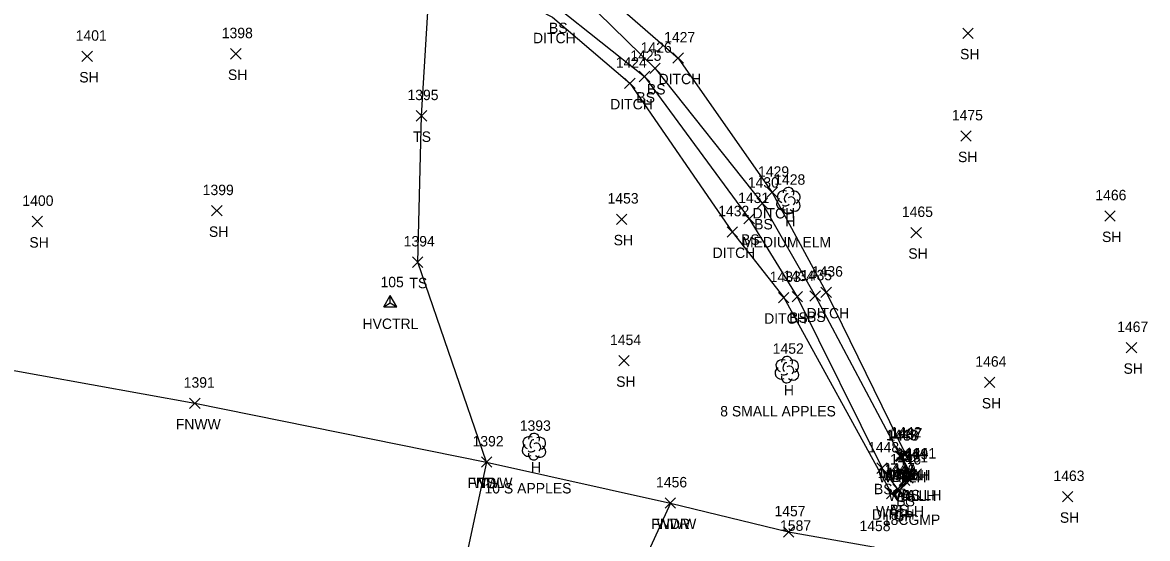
# Model space of a CAD drawing. Extents: x 1629176 to 1637209, y 606063 to 610167.
# Drawn here: x 1629563.1 to 1629778.6, y 606851.1 to 606950 of the extents above; entities that cross this region are included whole.
import ezdxf

# ---------------------------------------------------------------- set-up
doc = ezdxf.new("R2010")
doc.units = 0
for name, color, linetype in [('C_A', 7, 'Continuous'), ('C_I', 7, 'Continuous'), ('CPSM', 7, 'Continuous'), ('D_A', 7, 'Continuous'), ('D_C', 7, 'Continuous'), ('D_I', 7, 'Continuous'), ('D_TIC', 7, 'Continuous'), ('DD', 7, 'Continuous'), ('DHW', 7, 'Continuous'), ('L_A', 7, 'Continuous'), ('L_C', 7, 'Continuous'), ('L_I', 7, 'Continuous'), ('L_TIC', 7, 'Continuous'), ('LAWA', 7, 'Continuous'), ('LELB', 7, 'Continuous'), ('LFNC', 7, 'Continuous'), ('LTD', 7, 'Continuous'), ('R_A', 7, 'Continuous'), ('R_I', 7, 'Continuous'), ('RGP', 7, 'Continuous')]:
    doc.layers.add(name, color=color, linetype=linetype)

msp = doc.modelspace()

# ---------------------------------------------------------------- linework, layer by layer
at = {"layer": 'CPSM'}
for p, q in [((1629632.29, 606895.57), (1629633.54, 606897.73)), ((1629634.79, 606895.57), (1629633.54, 606897.73)), ((1629633.54, 606896.29), (1629633.54, 606897.73)), ((1629632.29, 606895.57), (1629633.54, 606896.29)), ((1629632.29, 606895.57), (1629634.79, 606895.57)), ((1629633.54, 606896.29), (1629633.54, 606896.29)), ((1629633.54, 606896.29), (1629634.79, 606895.57))]:
    msp.add_line(p, q, dxfattribs=at)
at = {"layer": 'D_TIC'}
for points in [[(1629687.69, 606942.21), (1629689.69, 606944.21)], [(1629689.69, 606942.21), (1629687.69, 606944.21)], [(1629678.43, 606937.38), (1629680.43, 606939.38)], [(1629680.43, 606937.38), (1629678.43, 606939.38)], [(1629705.7, 606916.47), (1629707.7, 606918.47)], [(1629707.7, 606916.47), (1629705.7, 606918.47)], [(1629698.06, 606908.9), (1629700.06, 606910.9)], [(1629700.06, 606908.9), (1629698.06, 606910.9)], [(1629716.05, 606897.33), (1629718.05, 606899.33)], [(1629718.05, 606897.33), (1629716.05, 606899.33)], [(1629707.92, 606896.3), (1629709.92, 606898.3)], [(1629709.92, 606896.3), (1629707.92, 606898.3)], [(1629730.48, 606865.89), (1629732.48, 606867.89)], [(1629732.48, 606865.89), (1629730.48, 606867.89)], [(1629731.2, 606866.29), (1629733.21, 606868.29)], [(1629733.21, 606866.29), (1629731.2, 606868.29)], [(1629731.2, 606866.29), (1629733.21, 606868.29)], [(1629733.21, 606866.29), (1629731.2, 606868.29)], [(1629731.71, 606861.74), (1629733.71, 606863.74)], [(1629733.71, 606861.74), (1629731.71, 606863.74)], [(1629732.34, 606862.35), (1629734.34, 606864.35)], [(1629734.34, 606862.35), (1629732.34, 606864.35)], [(1629733.3, 606862.47), (1629735.3, 606864.47)], [(1629735.3, 606862.47), (1629733.3, 606864.47)], [(1629728.58, 606858.74), (1629730.58, 606860.74)], [(1629730.58, 606858.74), (1629728.58, 606860.74)], [(1629730, 606859.35), (1629732, 606861.35)], [(1629732, 606859.35), (1629730, 606861.35)]]:
    msp.add_lwpolyline(points, dxfattribs=at)
at = {"layer": 'DD'}
for points in [[(1629579.49, 606988.83), (1629611.81, 606981.94), (1629648.15, 606971.51), (1629669.27, 606960.14), (1629688.69, 606943.21), (1629706.7, 606917.47), (1629717.05, 606898.33), (1629732.21, 606867.29)], [(1629578.34, 606981.92), (1629612.83, 606972), (1629644.13, 606961.63), (1629664.65, 606951.05), (1629679.43, 606938.38), (1629699.06, 606909.9), (1629708.92, 606897.3), (1629729.58, 606859.74)]]:
    msp.add_lwpolyline(points, dxfattribs=at)
at = {"layer": 'DHW'}
for points in [[(1629732.21, 606867.29), (1629731.48, 606866.89), (1629733.34, 606863.35), (1629731, 606860.35), (1629734.3, 606863.47)], [(1629734.3, 606863.47), (1629732.21, 606867.29)]]:
    msp.add_lwpolyline(points, dxfattribs=at)
at = {"layer": 'L_TIC'}
for points in [[(1629743.21, 606946.97), (1629745.21, 606948.97)], [(1629745.21, 606946.97), (1629743.21, 606948.97)], [(1629574.48, 606942.54), (1629576.48, 606944.54)], [(1629576.48, 606942.54), (1629574.48, 606944.54)], [(1629602.95, 606943.02), (1629604.95, 606945.02)], [(1629604.95, 606943.02), (1629602.95, 606945.02)], [(1629683.26, 606940.24), (1629685.26, 606942.24)], [(1629685.26, 606940.24), (1629683.26, 606942.24)], [(1629681.24, 606938.68), (1629683.24, 606940.68)], [(1629683.24, 606938.68), (1629681.24, 606940.68)], [(1629638.52, 606931.15), (1629640.52, 606933.15)], [(1629640.52, 606931.15), (1629638.52, 606933.15)], [(1629742.82, 606927.27), (1629744.82, 606929.27)], [(1629744.82, 606927.27), (1629742.82, 606929.27)], [(1629703.81, 606914.38), (1629705.81, 606916.38)], [(1629705.81, 606914.38), (1629703.81, 606916.38)], [(1629599.31, 606912.95), (1629601.31, 606914.95)], [(1629601.31, 606912.95), (1629599.31, 606914.95)], [(1629564.92, 606910.89), (1629566.92, 606912.89)], [(1629566.92, 606910.89), (1629564.92, 606912.89)], [(1629676.85, 606911.33), (1629678.85, 606913.33)], [(1629678.85, 606911.33), (1629676.85, 606913.33)], [(1629701.3, 606911.43), (1629703.3, 606913.43)], [(1629703.3, 606911.43), (1629701.3, 606913.43)], [(1629770.4, 606911.96), (1629772.4, 606913.96)], [(1629772.4, 606911.96), (1629770.4, 606913.96)], [(1629733.29, 606908.76), (1629735.29, 606910.76)], [(1629735.29, 606908.76), (1629733.29, 606910.76)], [(1629637.8, 606903.11), (1629639.8, 606905.11)], [(1629639.8, 606903.11), (1629637.8, 606905.11)], [(1629710.51, 606896.48), (1629712.51, 606898.48)], [(1629712.51, 606896.48), (1629710.51, 606898.48)], [(1629713.93, 606896.63), (1629715.93, 606898.63)], [(1629715.93, 606896.63), (1629713.93, 606898.63)], [(1629774.53, 606886.71), (1629776.53, 606888.71)], [(1629776.53, 606886.71), (1629774.53, 606888.71)], [(1629677.33, 606884.21), (1629679.33, 606886.21)], [(1629679.33, 606884.21), (1629677.33, 606886.21)], [(1629747.37, 606880.07), (1629749.37, 606882.07)], [(1629749.37, 606880.07), (1629747.37, 606882.07)], [(1629595.1, 606876.05), (1629597.1, 606878.05)], [(1629597.1, 606876.05), (1629595.1, 606878.05)], [(1629650.99, 606864.79), (1629652.99, 606866.79)], [(1629652.99, 606864.79), (1629650.99, 606866.79)], [(1629650.99, 606864.79), (1629652.99, 606866.79)], [(1629652.99, 606864.79), (1629650.99, 606866.79)], [(1629650.99, 606864.79), (1629652.99, 606866.79)], [(1629652.99, 606864.79), (1629650.99, 606866.79)], [(1629730.19, 606865.97), (1629732.19, 606867.97)], [(1629732.19, 606865.97), (1629730.19, 606867.97)], [(1629730.19, 606865.97), (1629732.19, 606867.97)], [(1629732.19, 606865.97), (1629730.19, 606867.97)], [(1629731.05, 606866.5), (1629733.05, 606868.5)], [(1629733.05, 606866.5), (1629731.05, 606868.5)], [(1629726.76, 606863.63), (1629728.76, 606865.63)], [(1629728.76, 606863.63), (1629726.76, 606865.63)], [(1629726.76, 606863.63), (1629728.76, 606865.63)], [(1629728.76, 606863.63), (1629726.76, 606865.63)], [(1629731.04, 606861.32), (1629733.04, 606863.32)], [(1629733.04, 606861.32), (1629731.04, 606863.32)], [(1629732.06, 606862.46), (1629734.06, 606864.46)], [(1629734.06, 606862.46), (1629732.06, 606864.46)], [(1629729.79, 606859.62), (1629731.79, 606861.62)], [(1629731.79, 606859.62), (1629729.79, 606861.62)], [(1629686.21, 606856.94), (1629688.21, 606858.94)], [(1629688.21, 606856.94), (1629686.21, 606858.94)], [(1629686.21, 606856.94), (1629688.21, 606858.94)], [(1629688.21, 606856.94), (1629686.21, 606858.94)], [(1629762.32, 606858.16), (1629764.32, 606860.16)], [(1629764.32, 606858.16), (1629762.32, 606860.16)], [(1629708.84, 606851.4), (1629710.84, 606853.4)], [(1629710.84, 606851.4), (1629708.84, 606853.4)]]:
    msp.add_lwpolyline(points, dxfattribs=at)
at = {"layer": 'LAWA'}
for points in [[(1629651.99, 606865.79), (1629643.99, 606828.57), (1629642.89, 606813.88), (1629664.41, 606817.56), (1629675.67, 606832.68)], [(1629687.21, 606857.94), (1629675.67, 606832.68)]]:
    msp.add_lwpolyline(points, dxfattribs=at)
at = {"layer": 'LELB'}
for points in [[(1629651.99, 606865.79), (1629638.8, 606904.11), (1629639.52, 606932.15), (1629641.08, 606957.38), (1629605.09, 606970.25), (1629580.18, 606977), (1629580.06, 606977.06), (1629573.73, 606982), (1629574.6, 606989.84), (1629579.49, 606988.83)], [(1629578.44, 606986.01), (1629578.11, 606983.58), (1629612.04, 606975.09), (1629645.79, 606965.11), (1629665.51, 606952.99), (1629682.24, 606939.68), (1629702.3, 606912.43), (1629711.51, 606897.48), (1629727.76, 606864.63)], [(1629578.44, 606986.01), (1629611.74, 606978.59), (1629646.94, 606968.36), (1629667.85, 606957.32), (1629684.26, 606941.24), (1629704.81, 606915.38), (1629714.93, 606897.63), (1629731.19, 606866.97), (1629733.06, 606863.46), (1629732.04, 606862.32), (1629730.79, 606860.62), (1629727.76, 606864.63)], [(1629732.05, 606867.5), (1629731.19, 606866.97)]]:
    msp.add_lwpolyline(points, dxfattribs=at)
at = {"layer": 'LFNC'}
msp.add_lwpolyline([(1629193.07, 606917.87), (1629225.59, 606916.68), (1629272.22, 606914.37), (1629291.9, 606913.28), (1629328.76, 606910.62), (1629372.75, 606906.84), (1629412.15, 606903.01), (1629459.35, 606897.68), (1629481.55, 606894.63), (1629529.36, 606888.4), (1629556.45, 606884.22), (1629596.1, 606877.05), (1629651.99, 606865.79), (1629687.21, 606857.94), (1629709.84, 606852.4), (1629726.11, 606849.55), (1629738.25, 606845.85), (1629771.23, 606838.25)], dxfattribs=at)
at = {"layer": 'LTD'}
for p, q in [((1629709.79, 606915.94), (1629709.79, 606915.94)), ((1629709.79, 606915.94), (1629709.79, 606915.94)), ((1629709.5, 606883.55), (1629709.5, 606883.55)), ((1629709.5, 606883.55), (1629709.5, 606883.55)), ((1629661.04, 606868.78), (1629661.04, 606868.78)), ((1629661.04, 606868.78), (1629661.04, 606868.78))]:
    msp.add_line(p, q, dxfattribs=at)
for centre in [(1629709.83, 606917.38), (1629709.55, 606884.98), (1629661.09, 606870.21)]:
    msp.add_arc(centre, 1.05, 335.5272, 180.9563, dxfattribs=at)
for centre, major_axis, ratio, start_param, end_param in [((1629708.7, 606915.23), (0.58, -1.04), 0.959034, 3.141593, 6.283185), ((1629709, 606916.61), (1.21, -0.51), 0.895232, 1.570796, 4.712389), ((1629709.58, 606916.4), (-0.208, -0.792), 0.645439, 3.141593, 6.283185), ((1629710.29, 606915.77), (-0.5, 0.667), 0.989748, 3.141593, 6.283185), ((1629710.83, 606916.52), (-1.14, -0.48), 0.949671, 1.570796, 4.712389), ((1629709.79, 606914.44), (0.26, 1.06), 0.942809, 1.570796, 4.712389), ((1629709.33, 606915.19), (-0.625, -0.083), 0.423636, 0, 3.141593), ((1629710.79, 606915.11), (-1.09, 0.79), 0.841452, 1.570796, 4.712389), ((1629708.71, 606884.21), (1.21, -0.51), 0.895232, 1.570796, 4.712389), ((1629709.29, 606884), (-0.208, -0.792), 0.645439, 3.141593, 6.283185), ((1629710, 606883.38), (-0.5, 0.667), 0.989748, 3.141593, 6.283185), ((1629710.54, 606884.13), (-1.14, -0.48), 0.949671, 1.570796, 4.712389), ((1629708.42, 606882.84), (0.58, -1.04), 0.959034, 3.141593, 6.283185), ((1629709.5, 606882.05), (0.26, 1.06), 0.942809, 1.570796, 4.712389), ((1629709.04, 606882.79), (-0.625, -0.083), 0.423636, 0, 3.141593), ((1629710.5, 606882.71), (-1.09, 0.79), 0.841452, 1.570796, 4.712389), ((1629659.96, 606868.07), (0.58, -1.04), 0.959034, 3.141593, 6.283185), ((1629660.25, 606869.45), (1.21, -0.51), 0.895232, 1.570796, 4.712389), ((1629660.83, 606869.24), (-0.208, -0.792), 0.645439, 3.141593, 6.283185), ((1629661.54, 606868.61), (-0.5, 0.667), 0.989748, 3.141593, 6.283185), ((1629662.04, 606867.95), (-1.09, 0.79), 0.841452, 1.570796, 4.712389), ((1629662.08, 606869.36), (-1.14, -0.48), 0.949671, 1.570796, 4.712389), ((1629661.04, 606867.28), (0.26, 1.06), 0.942809, 1.570796, 4.712389), ((1629660.58, 606868.03), (-0.625, -0.083), 0.423636, 0, 3.141593)]:
    msp.add_ellipse(centre, major_axis=major_axis, ratio=ratio, start_param=start_param, end_param=end_param, dxfattribs=at)
at = {"layer": 'RGP'}
msp.add_line((1629731.51, 606859.42), (1629731.51, 606859.42), dxfattribs=at)
for radius in [1.25, 0.0833]:
    msp.add_circle((1629731.51, 606859.42), radius, dxfattribs=at)

# ---------------------------------------------------------------- texts
at = {"layer": 'C_A'}
msp.add_text('HVCTRL', height=2, dxfattribs=at).set_placement((1629628.23, 606891.29))
at = {"layer": 'C_I'}
msp.add_text('105', height=2, dxfattribs=at).set_placement((1629631.67, 606899.29))
at = {"layer": 'D_A'}
for s, p in [('DITCH', (1629660.89, 606946.05)), ('DITCH', (1629684.93, 606938.21)), ('DITCH', (1629675.67, 606933.38)), ('DITCH', (1629702.94, 606912.47)), ('DITCH', (1629695.29, 606904.9)), ('DITCH', (1629713.29, 606893.33)), ('DITCH', (1629705.16, 606892.3)), ('WALLH', (1629727.07, 606861.89)), ('WALLH', (1629727.8, 606862.29)), ('DITCH', (1629728.44, 606862.29)), ('WALLH', (1629728.93, 606858.35)), ('WALLH', (1629729.89, 606858.47)), ('P', (1629732.09, 606857.74)), ('DITCH', (1629725.82, 606854.74)), ('WALLH', (1629726.59, 606855.35))]:
    msp.add_text(s, height=2, dxfattribs=at).set_placement(p)
at = {"layer": 'D_C'}
msp.add_text('18CGMP', height=2, dxfattribs=at).set_placement((1629727.9, 606853.74))
at = {"layer": 'D_I'}
for s, p in [('1427', (1629686, 606946.21)), ('1424', (1629676.74, 606941.38)), ('1429', (1629704, 606920.47)), ('1432', (1629696.36, 606912.9)), ('1436', (1629714.3, 606901.33)), ('1433', (1629706.23, 606900.3)), ('1438', (1629728.79, 606869.89)), ('1437', (1629729.51, 606870.29)), ('1437', (1629729.51, 606870.29)), ('1451', (1629730.59, 606865.74)), ('1439', (1629730.64, 606866.35)), ('1441', (1629732.17, 606866.47)), ('1449', (1629726.88, 606862.74)), ('1440', (1629728.22, 606863.35))]:
    msp.add_text(s, height=2, dxfattribs=at).set_placement(p)
at = {"layer": 'L_A'}
for s, p in [('BS', (1629663.95, 606947.99)), ('SH', (1629742.7, 606942.97)), ('SH', (1629573.97, 606938.54)), ('SH', (1629602.44, 606939.02)), ('BS', (1629682.7, 606936.24)), ('BS', (1629680.68, 606934.68)), ('TS', (1629637.93, 606927.15)), ('SH', (1629742.3, 606923.27)), ('BS', (1629703.25, 606910.38)), ('H', (1629709.22, 606910.94)), ('SH', (1629598.8, 606908.95)), ('SH', (1629769.89, 606907.96)), ('SH', (1629564.41, 606906.89)), ('SH', (1629676.34, 606907.33)), ('BS', (1629700.74, 606907.43)), ('SH', (1629732.78, 606904.76)), ('TS', (1629637.21, 606899.11)), ('BS', (1629713.37, 606892.63)), ('BS', (1629709.95, 606892.48)), ('SH', (1629774.01, 606882.71)), ('SH', (1629676.82, 606880.21)), ('H', (1629708.94, 606878.55)), ('SH', (1629746.86, 606876.07)), ('FNWW', (1629592.45, 606872.05)), ('H', (1629660.48, 606863.78)), ('BS', (1629730.49, 606862.5)), ('FNWW', (1629648.33, 606860.79)), ('WDL', (1629649.41, 606860.79)), ('TS', (1629650.4, 606860.79)), ('BS', (1629729.63, 606861.97)), ('BS', (1629729.63, 606861.97)), ('BS', (1629726.2, 606859.63)), ('BS', (1629726.2, 606859.63)), ('BS', (1629731.5, 606858.46)), ('BS', (1629730.48, 606857.32)), ('BS', (1629729.23, 606855.62)), ('SH', (1629761.81, 606854.16)), ('FNWW', (1629683.55, 606852.94)), ('WDR', (1629684.57, 606852.94))]:
    msp.add_text(s, height=2, dxfattribs=at).set_placement(p)
at = {"layer": 'L_C'}
for s, p in [('MEDIUM ELM', (1629700.91, 606906.94)), ('8 SMALL APPLES', (1629696.75, 606874.54)), ('10 S APPLES', (1629651.59, 606859.78))]:
    msp.add_text(s, height=2, dxfattribs=at).set_placement(p)
at = {"layer": 'L_I'}
for s, p in [('1401', (1629573.28, 606946.54)), ('1398', (1629601.26, 606947.02)), ('1425', (1629679.54, 606942.68)), ('1426', (1629681.51, 606944.24)), ('1395', (1629636.83, 606935.15)), ('1475', (1629741.12, 606931.27)), ('1428', (1629707.09, 606918.94)), ('1399', (1629597.61, 606916.95)), ('1430', (1629702.03, 606918.38)), ('1400', (1629563.07, 606914.89)), ('1453', (1629675.16, 606915.33)), ('1431', (1629700.18, 606915.43)), ('1466', (1629768.61, 606915.96)), ('1465', (1629731.55, 606912.76)), ('1394', (1629636.11, 606907.11)), ('1434', (1629708.81, 606900.48)), ('1435', (1629712.23, 606900.63)), ('1467', (1629772.79, 606890.71)), ('1454', (1629675.64, 606888.21)), ('1452', (1629706.81, 606886.54)), ('1464', (1629745.63, 606884.07)), ('1391', (1629593.97, 606880.05)), ('1393', (1629658.35, 606871.78)), ('1443', (1629728.5, 606869.97)), ('1443', (1629728.5, 606869.97)), ('1442', (1629729.36, 606870.5)), ('1392', (1629649.3, 606868.79)), ('1392', (1629649.3, 606868.79)), ('1392', (1629649.3, 606868.79)), ('1448', (1629725.07, 606867.63)), ('1448', (1629725.07, 606867.63)), ('1446', (1629729.29, 606865.32)), ('1444', (1629730.37, 606866.46)), ('1447', (1629728.1, 606863.62)), ('1456', (1629684.46, 606860.94)), ('1456', (1629684.46, 606860.94)), ('1463', (1629760.58, 606862.16)), ('1457', (1629707.14, 606855.4)), ('1587', (1629708.21, 606852.62)), ('1458', (1629723.42, 606852.55))]:
    msp.add_text(s, height=2, dxfattribs=at).set_placement(p)
at = {"layer": 'R_A'}
msp.add_text('GP', height=2, dxfattribs=at).set_placement((1629729.94, 606854.42))
at = {"layer": 'R_I'}
msp.add_text('1450', height=2, dxfattribs=at).set_placement((1629728.73, 606862.42))

doc.saveas('drawing.dxf')
